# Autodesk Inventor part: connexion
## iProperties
Author: chr
Created: 2001-06
Part Number: connexion
Material: Par défaut
Document SubType Name: Modélisation
Designer: chr
Control State: 0
Master: False
Checked Out: False
PropertySet Name: Design Tracking Control
Shininess: 21.0
PropertySet Name: _Private Model Information
Length Units: 11269
Angle Units: 11286
Time Units: 11279
Mass Units: 11290
Length Display Precision: 3
Angle Display Precision: 2
Compacted: False
Density: 0.0
Volumn: 0.0
Area: 0.0
PropertySet Name: Model Information
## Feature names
1. Extrusion1
